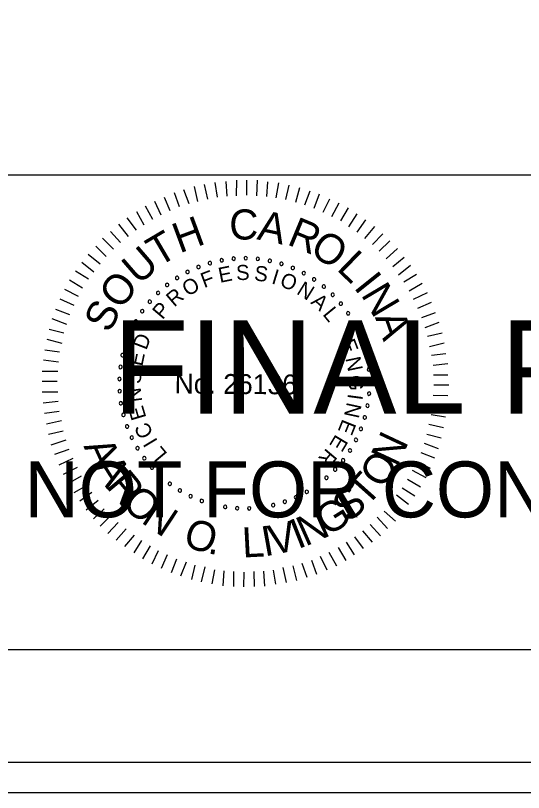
# Model space of a CAD drawing. Extents: x 967 to 1623, y 964 to 7064.
# Drawn here: x 1170.56 to 1189.3, y 6843.72 to 6872.36 of the extents above; entities that cross this region are included whole.
import ezdxf

# ---------------------------------------------------------------- set-up
doc = ezdxf.new("R2010")
doc.units = 0
for name, color, linetype in [('RD_SHT_Bndy', 7, 'Continuous'), ('RD_SHT_IplotShp', 7, 'Continuous'), ('RD_SHT_Misc1', 7, 'Continuous'), ('RD_SHT_Misc2', 7, 'Continuous'), ('RD_Sketch1', 7, 'Continuous')]:
    doc.layers.add(name, color=color, linetype=linetype)

msp = doc.modelspace()

# ---------------------------------------------------------------- linework, layer by layer
at = {"layer": 'RD_SHT_Bndy'}
for p, q in [((996.114, 6866.486), (1323.886, 6866.486)), ((1323.886, 6848.983), (996.114, 6848.983))]:
    msp.add_line(p, q, dxfattribs=at)
at = {"layer": 'RD_SHT_IplotShp'}
for points in [[(967.409, 6843.72), (1326.285, 6843.72), (1326.285, 7063.72), (967.409, 7063.72)], [(988.525, 6844.84), (1326.285, 6844.84), (1326.285, 7062.6), (988.525, 7062.6)]]:
    msp.add_lwpolyline(points, close=True, dxfattribs=at)
at = {"layer": 'RD_SHT_Misc1'}
for p, q in [((1177.657, 6865.597), (1177.53, 6866.128)), ((1178.01, 6865.663), (1177.93, 6866.209)), ((1178.364, 6865.699), (1178.33, 6866.244)), ((1178.717, 6865.719), (1178.722, 6866.295)), ((1179.093, 6865.739), (1179.098, 6866.292)), ((1179.469, 6865.713), (1179.489, 6866.288)), ((1179.829, 6865.687), (1179.872, 6866.231)), ((1180.174, 6865.646), (1180.271, 6866.19)), ((1180.535, 6865.573), (1180.662, 6866.102)), ((1176.61, 6865.306), (1176.423, 6865.83)), ((1176.964, 6865.419), (1176.769, 6865.935)), ((1177.287, 6865.508), (1177.169, 6866.054)), ((1180.902, 6865.478), (1181.045, 6866.022)), ((1181.231, 6865.384), (1181.428, 6865.896)), ((1176.264, 6865.156), (1176.053, 6865.657)), ((1181.584, 6865.265), (1181.78, 6865.786)), ((1181.905, 6865.109), (1182.154, 6865.606)), ((1175.624, 6864.846), (1175.352, 6865.332)), ((1175.933, 6865.005), (1175.699, 6865.506)), ((1182.226, 6864.953), (1182.506, 6865.45)), ((1182.562, 6864.789), (1182.85, 6865.27)), ((1175.308, 6864.634), (1175.036, 6865.12)), ((1182.86, 6864.572), (1183.163, 6865.053)), ((1174.729, 6864.217), (1174.372, 6864.665)), ((1175.03, 6864.445), (1174.681, 6864.9)), ((1183.158, 6864.378), (1183.484, 6864.828)), ((1174.435, 6863.997), (1174.062, 6864.399)), ((1183.447, 6864.145), (1183.811, 6864.587)), ((1174.172, 6863.753), (1173.776, 6864.148)), ((1183.729, 6863.92), (1184.116, 6864.316)), ((1173.909, 6863.479), (1173.52, 6863.858)), ((1183.98, 6863.672), (1184.368, 6864.061)), ((1173.684, 6863.197), (1173.242, 6863.546)), ((1184.232, 6863.394), (1184.657, 6863.767)), ((1173.451, 6862.9), (1173.009, 6863.256)), ((1184.475, 6863.108), (1184.892, 6863.45)), ((1184.687, 6862.807), (1185.128, 6863.156)), ((1173.257, 6862.64), (1172.776, 6862.936)), ((1184.885, 6862.544), (1185.355, 6862.832)), ((1173.039, 6862.312), (1172.559, 6862.6)), ((1185.081, 6862.213), (1185.56, 6862.493)), ((1172.883, 6862.006), (1172.379, 6862.256)), ((1185.24, 6861.904), (1185.756, 6862.145)), ((1172.727, 6861.677), (1172.215, 6861.904)), ((1172.571, 6861.333), (1172.051, 6861.53)), ((1185.399, 6861.573), (1185.907, 6861.791)), ((1185.549, 6861.226), (1186.057, 6861.414)), ((1172.461, 6860.974), (1171.91, 6861.178)), ((1185.669, 6860.865), (1186.185, 6861.06)), ((1172.351, 6860.652), (1171.807, 6860.787)), ((1185.759, 6860.541), (1186.297, 6860.667)), ((1172.286, 6860.276), (1171.727, 6860.419)), ((1185.832, 6860.165), (1186.371, 6860.298)), ((1172.191, 6859.955), (1171.647, 6860.029)), ((1185.906, 6859.842), (1186.436, 6859.906)), ((1172.15, 6859.587), (1171.598, 6859.653)), ((1185.964, 6859.473), (1186.51, 6859.53)), ((1172.124, 6859.234), (1171.548, 6859.239)), ((1185.977, 6859.12), (1186.514, 6859.115)), ((1172.105, 6858.866), (1171.545, 6858.871)), ((1185.997, 6858.751), (1186.542, 6858.747)), ((1172.118, 6858.482), (1171.542, 6858.471)), ((1185.971, 6858.368), (1186.508, 6858.348)), ((1172.138, 6858.136), (1171.585, 6858.072)), ((1185.952, 6858.022), (1186.497, 6857.949)), ((1172.173, 6857.768), (1171.627, 6857.688)), ((1185.888, 6857.655), (1186.417, 6857.566)), ((1172.262, 6857.414), (1171.701, 6857.296)), ((1185.808, 6857.302), (1186.345, 6857.175)), ((1172.321, 6857.037), (1171.774, 6856.911)), ((1172.425, 6856.707), (1171.871, 6856.519)), ((1185.729, 6856.926), (1186.265, 6856.792)), ((1172.53, 6856.36), (1172.007, 6856.173)), ((1185.634, 6856.597), (1186.146, 6856.401)), ((1185.508, 6856.253), (1186.013, 6856.057)), ((1172.681, 6856.029), (1172.165, 6855.788)), ((1185.352, 6855.924), (1185.857, 6855.675)), ((1172.831, 6855.705), (1172.323, 6855.441)), ((1185.188, 6855.603), (1185.7, 6855.33)), ((1172.982, 6855.374), (1172.497, 6855.094)), ((1185.024, 6855.274), (1185.498, 6854.987)), ((1173.194, 6855.042), (1172.709, 6854.762)), ((1184.822, 6854.946), (1185.288, 6854.658)), ((1173.384, 6854.78), (1172.936, 6854.453)), ((1184.62, 6854.687), (1185.055, 6854.353)), ((1173.612, 6854.478), (1173.164, 6854.129)), ((1184.403, 6854.389), (1184.814, 6854.033)), ((1173.832, 6854.177), (1173.437, 6853.812)), ((1184.155, 6854.092), (1184.574, 6853.72)), ((1174.091, 6853.945), (1173.689, 6853.541)), ((1183.899, 6853.864), (1184.28, 6853.454)), ((1174.35, 6853.674), (1173.97, 6853.263)), ((1183.644, 6853.597), (1184.024, 6853.18)), ((1174.64, 6853.442), (1174.275, 6853.022)), ((1174.937, 6853.209), (1174.58, 6852.782)), ((1183.358, 6853.37), (1183.715, 6852.944)), ((1175.212, 6853.014), (1174.932, 6852.549)), ((1182.764, 6852.952), (1183.059, 6852.482)), ((1183.065, 6853.141), (1183.384, 6852.709)), ((1175.525, 6852.812), (1175.245, 6852.331)), ((1182.463, 6852.755), (1182.743, 6852.269)), ((1175.83, 6852.633), (1175.588, 6852.136)), ((1176.159, 6852.477), (1175.94, 6851.98)), ((1181.8, 6852.431), (1182.041, 6851.93)), ((1182.124, 6852.581), (1182.396, 6852.08)), ((1176.503, 6852.321), (1176.307, 6851.816)), ((1176.855, 6852.211), (1176.651, 6851.69)), ((1177.177, 6852.1), (1177.05, 6851.572)), ((1180.791, 6852.07), (1180.926, 6851.54)), ((1181.122, 6852.175), (1181.31, 6851.652)), ((1181.476, 6852.28), (1181.664, 6851.771)), ((1177.545, 6852.036), (1177.409, 6851.484)), ((1177.897, 6851.933), (1177.808, 6851.412)), ((1178.25, 6851.892), (1178.207, 6851.34)), ((1178.603, 6851.866), (1178.598, 6851.313)), ((1178.978, 6851.84), (1178.974, 6851.295)), ((1179.355, 6851.86), (1179.365, 6851.307)), ((1179.715, 6851.88), (1179.749, 6851.327)), ((1180.061, 6851.915), (1180.149, 6851.393)), ((1180.423, 6852.012), (1180.541, 6851.458))]:
    msp.add_line(p, q, dxfattribs=at)
for centre, start, end in [((1177.734, 6863.235), 16.1422, 196.1422), ((1177.734, 6863.235), 196.1422, 16.1422), ((1178.168, 6863.337), 10.6038, 190.6038), ((1178.168, 6863.337), 190.6038, 10.6038), ((1178.609, 6863.397), 5.0653, 185.0653), ((1178.609, 6863.397), 185.0653, 5.0653), ((1179.055, 6863.414), 359.5268, 179.5268), ((1179.055, 6863.414), 179.5268, 359.5268), ((1179.5, 6863.388), 353.9884, 173.9884), ((1179.5, 6863.388), 173.9884, 353.9884), ((1179.94, 6863.319), 168.4499, 348.4499), ((1179.94, 6863.319), 348.4499, 168.4499), ((1180.372, 6863.208), 342.9114, 162.9114), ((1176.906, 6862.908), 27.2191, 207.2191), ((1177.312, 6863.091), 21.6807, 201.6807), ((1177.312, 6863.091), 201.6807, 21.6807), ((1180.372, 6863.208), 162.9114, 342.9114), ((1180.79, 6863.056), 157.373, 337.373), ((1180.79, 6863.056), 337.373, 157.373), ((1176.52, 6862.686), 32.7576, 212.7576), ((1176.52, 6862.686), 212.7576, 32.7576), ((1176.906, 6862.908), 207.2191, 27.2191), ((1181.193, 6862.864), 151.8345, 331.8345), ((1181.193, 6862.864), 331.8345, 151.8345), ((1181.574, 6862.634), 146.2961, 326.2961), ((1181.574, 6862.634), 326.2961, 146.2961), ((1176.156, 6862.428), 38.2961, 218.2961), ((1176.156, 6862.428), 218.2961, 38.2961), ((1181.932, 6862.368), 140.7576, 320.7576), ((1181.932, 6862.368), 320.7576, 140.7576), ((1175.82, 6862.135), 43.8345, 223.8345), ((1175.82, 6862.135), 223.8345, 43.8345), ((1182.263, 6862.069), 135.2191, 315.2191), ((1182.263, 6862.069), 315.2191, 135.2191), ((1175.513, 6861.812), 49.373, 229.373), ((1175.513, 6861.812), 229.373, 49.373), ((1182.563, 6861.74), 309.6807, 129.6807), ((1175.239, 6861.461), 54.9114, 234.9114), ((1182.563, 6861.74), 129.6807, 309.6807), ((1175.239, 6861.461), 234.9114, 54.9114), ((1182.83, 6861.383), 124.1422, 304.1422), ((1182.83, 6861.383), 304.1422, 124.1422), ((1175, 6861.085), 60.4499, 240.4499), ((1175, 6861.085), 240.4499, 60.4499), ((1183.061, 6861.002), 118.6038, 298.6038), ((1183.061, 6861.002), 298.6038, 118.6038), ((1174.798, 6860.687), 65.9884, 245.9884), ((1174.798, 6860.687), 245.9884, 65.9884), ((1183.255, 6860.601), 113.0653, 293.0653), ((1183.255, 6860.601), 293.0653, 113.0653), ((1174.636, 6860.272), 71.5268, 251.5268), ((1174.636, 6860.272), 251.5268, 71.5268), ((1183.408, 6860.182), 107.5268, 287.5268), ((1183.408, 6860.182), 287.5268, 107.5268), ((1174.514, 6859.843), 77.0653, 257.0653), ((1174.514, 6859.843), 257.0653, 77.0653), ((1183.521, 6859.751), 101.9884, 281.9884), ((1183.521, 6859.751), 281.9884, 101.9884), ((1174.435, 6859.405), 82.6038, 262.6038), ((1174.435, 6859.405), 262.6038, 82.6038), ((1183.592, 6859.311), 96.4499, 276.4499), ((1183.592, 6859.311), 276.4499, 96.4499), ((1174.398, 6858.961), 88.1422, 268.1422), ((1174.398, 6858.961), 268.1422, 88.1422), ((1183.619, 6858.866), 90.9114, 270.9114), ((1183.619, 6858.866), 270.9114, 90.9114), ((1174.404, 6858.515), 93.6807, 273.6807), ((1174.404, 6858.515), 273.6807, 93.6807), ((1183.604, 6858.421), 85.373, 265.373), ((1183.604, 6858.421), 265.373, 85.373), ((1174.453, 6858.072), 99.2191, 279.2191), ((1174.453, 6858.072), 279.2191, 99.2191), ((1183.546, 6857.979), 79.8345, 259.8345), ((1183.546, 6857.979), 259.8345, 79.8345), ((1174.545, 6857.636), 104.7576, 284.7576), ((1174.545, 6857.636), 284.7576, 104.7576), ((1183.445, 6857.545), 74.2961, 254.2961), ((1183.445, 6857.545), 254.2961, 74.2961), ((1174.678, 6857.211), 110.2961, 290.2961), ((1174.678, 6857.211), 290.2961, 110.2961), ((1183.303, 6857.122), 68.7576, 248.7576), ((1183.303, 6857.122), 248.7576, 68.7576), ((1174.852, 6856.8), 115.8345, 295.8345), ((1174.852, 6856.8), 295.8345, 115.8345), ((1183.121, 6856.716), 63.2191, 243.2191), ((1183.121, 6856.716), 243.2191, 63.2191), ((1175.065, 6856.409), 121.373, 301.373), ((1175.065, 6856.409), 301.373, 121.373), ((1182.9, 6856.328), 57.6807, 237.6807), ((1182.9, 6856.328), 237.6807, 57.6807), ((1175.314, 6856.039), 126.9114, 306.9114), ((1175.314, 6856.039), 306.9114, 126.9114), ((1182.643, 6855.964), 52.1422, 232.1422), ((1182.643, 6855.964), 232.1422, 52.1422), ((1175.598, 6855.696), 132.4499, 312.4499), ((1175.598, 6855.696), 312.4499, 132.4499), ((1182.353, 6855.627), 46.6038, 226.6038), ((1182.353, 6855.627), 226.6038, 46.6038), ((1175.914, 6855.381), 137.9884, 317.9884), ((1175.914, 6855.381), 317.9884, 137.9884), ((1182.03, 6855.319), 41.0653, 221.0653), ((1182.03, 6855.319), 221.0653, 41.0653), ((1176.258, 6855.099), 143.5268, 323.5268), ((1176.258, 6855.099), 323.5268, 143.5268), ((1181.68, 6855.043), 35.5268, 215.5268), ((1181.68, 6855.043), 215.5268, 35.5268), ((1176.629, 6854.851), 149.0653, 329.0653), ((1176.629, 6854.851), 329.0653, 149.0653), ((1177.021, 6854.639), 154.6038, 334.6038), ((1177.021, 6854.639), 334.6038, 154.6038), ((1180.908, 6854.6), 24.4499, 204.4499), ((1181.305, 6854.803), 29.9884, 209.9884), ((1181.305, 6854.803), 209.9884, 29.9884), ((1177.432, 6854.467), 160.1422, 340.1422), ((1177.432, 6854.467), 340.1422, 160.1422), ((1177.858, 6854.335), 345.6807, 165.6807), ((1180.065, 6854.313), 13.373, 193.373), ((1180.494, 6854.436), 18.9114, 198.9114), ((1180.494, 6854.436), 198.9114, 18.9114), ((1180.908, 6854.6), 204.4499, 24.4499), ((1177.858, 6854.335), 165.6807, 345.6807), ((1178.294, 6854.245), 351.2191, 171.2191), ((1178.294, 6854.245), 171.2191, 351.2191), ((1178.737, 6854.198), 356.7576, 176.7576), ((1178.737, 6854.198), 176.7576, 356.7576), ((1179.183, 6854.193), 2.2961, 182.2961), ((1179.183, 6854.193), 182.2961, 2.2961), ((1179.627, 6854.232), 7.8345, 187.8345), ((1179.627, 6854.232), 187.8345, 7.8345), ((1180.065, 6854.313), 193.373, 13.373)]:
    msp.add_arc(centre, 0.0627, start, end, dxfattribs=at)
at = {"layer": 'RD_Sketch1'}
msp.add_lwpolyline([(967.409, 6843.72), (1326.285, 6843.72), (1326.285, 7063.72), (967.409, 7063.72)], close=True, dxfattribs=at)

# ---------------------------------------------------------------- texts
at = {"layer": 'RD_SHT_Misc1'}
for s, height, rotation, p in [('H', 1.11, 20.3637, (1176.614, 6863.587)), ('C', 1.11, 359.5482, (1178.442, 6864.108)), ('A', 1.11, 348.1981, (1179.439, 6864.115)), ('R', 1.11, 337.4344, (1180.541, 6863.937)), ('T', 1.11, 30.4992, (1175.828, 6863.072)), ('O', 1.108, 326.5869, (1181.366, 6863.609)), ('U', 1.11, 40.8022, (1175.102, 6862.403)), ('L', 1.11, 315.9488, (1182.373, 6863.003)), ('F', 0.557, 20.6127, (1177.52, 6862.309)), ('E', 0.557, 11.4103, (1178.103, 6862.503)), ('S', 0.557, 2.208, (1178.709, 6862.601)), ('S', 0.557, 352.6608, (1179.346, 6862.599)), ('I', 0.557, 343.1136, (1179.975, 6862.491)), ('O', 1.11, 52.0267, (1174.435, 6861.474)), ('O', 0.557, 30.8477, (1176.917, 6861.987)), ('O', 0.557, 338.4392, (1180.274, 6862.401)), ('I', 1.11, 308.6613, (1183.011, 6862.338)), ('N', 0.557, 328.2042, (1180.896, 6862.12)), ('N', 1.11, 300.7037, (1183.285, 6862.075)), ('R', 0.557, 40.3949, (1176.415, 6861.594)), ('S', 1.108, 63.2511, (1174.029, 6860.619)), ('A', 0.557, 318.657, (1181.424, 6861.762)), ('P', 0.557, 49.9421, (1175.985, 6861.124)), ('L', 0.557, 309.4546, (1181.869, 6861.339)), ('A', 1.11, 289.4792, (1183.814, 6861.243)), ('D', 0.557, 69.0364, (1175.386, 6860.003)), ('E', 0.557, 291.049, (1182.53, 6860.307)), ('E', 0.557, 78.2388, (1175.238, 6859.407)), ('N', 0.557, 281.8466, (1182.728, 6859.726)), ('S', 0.557, 87.786, (1175.187, 6858.772)), ('No. 26136', 0.7311, 359.5268, (1176.429, 6858.43)), ('G', 0.557, 272.2995, (1182.833, 6859.097)), ('N', 0.557, 97.3332, (1175.242, 6858.137)), ('I', 0.557, 262.4084, (1182.83, 6858.437)), ('E', 0.557, 106.5355, (1175.394, 6857.541)), ('N', 0.557, 257.7339, (1182.789, 6858.127)), ('C', 0.557, 116.4266, (1175.661, 6856.938)), ('E', 0.557, 248.1867, (1182.628, 6857.511)), ('N', 1.105, 64.8922, (1184.632, 6855.684)), ('I', 0.557, 121.1011, (1175.823, 6856.67)), ('E', 0.557, 238.9844, (1182.378, 6856.949)), ('A', 1.105, 294.7297, (1173.062, 6856.486)), ('L', 0.557, 129.9595, (1176.187, 6856.204)), ('R', 0.557, 229.782, (1182.041, 6856.435)), ('O', 1.105, 56.2059, (1184.102, 6854.874)), ('A', 1.105, 302.2892, (1173.414, 6855.72)), ('R', 1.105, 309.8487, (1173.865, 6855.007)), ('T', 1.105, 48.2685, (1183.515, 6854.211)), ('O', 1.105, 317.7861, (1174.434, 6854.33)), ('S', 1.105, 40.3311, (1182.842, 6853.636)), ('N', 1.105, 326.4725, (1175.158, 6853.686)), ('G', 1.105, 32.0198, (1182.059, 6853.14)), ('N', 1.105, 24.0824, (1181.252, 6852.776)), ('O', 1.105, 342.3472, (1176.697, 6852.82)), ('I', 1.105, 21.4605, (1180.976, 6852.681)), ('L', 1.105, 2.9677, (1178.943, 6852.379)), ('I', 1.105, 10.1523, (1179.743, 6852.418)), ('V', 1.105, 12.7741, (1180.033, 6852.457)), ('.', 1.105, 351.0336, (1177.623, 6852.536))]:
    msp.add_text(s, height=height, rotation=rotation, dxfattribs=at).set_placement(p)
at = {"layer": 'RD_SHT_Misc2'}
for s, height, p in [('FINAL PLANS', 3.4375, (1174.145, 6857.685)), ('NOT FOR CONSTRUCTION', 2.0625, (1170.901, 6853.86))]:
    msp.add_text(s, height=height, dxfattribs=at).set_placement(p)

doc.saveas('drawing.dxf')
